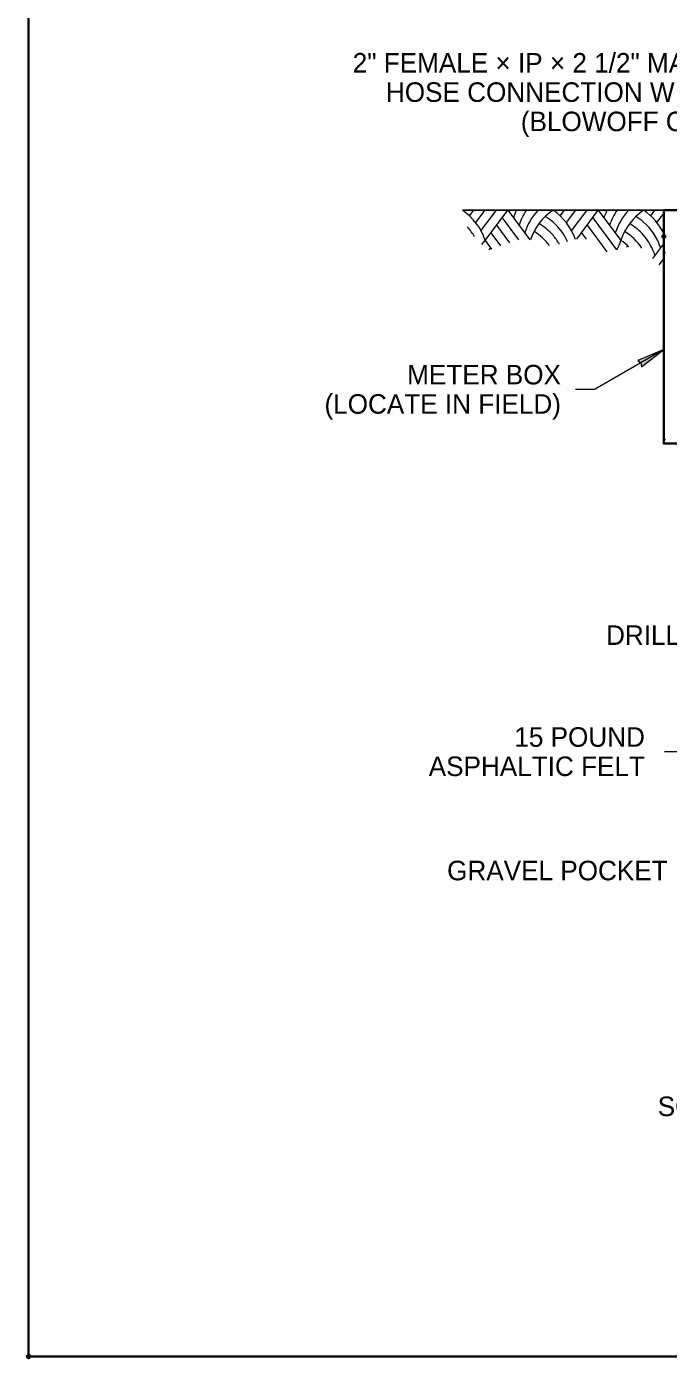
# Model space of a CAD drawing. Extents: x 99860 to 103153, y 99998 to 102077.
# Drawn here: x 99860 to 100386, y 99998 to 101089 of the extents above; entities that cross this region are included whole.
import ezdxf
from ezdxf.enums import TextEntityAlignment as Align

# ---------------------------------------------------------------- set-up
doc = ezdxf.new("R2010")
doc.units = 0
doc.header["$LTSCALE"] = 6.4
doc.header["$PDMODE"] = 32
doc.header["$PDSIZE"] = 3.2
for name, color, linetype, lineweight in [('1', 7, 'Continuous', 13), ('10', 7, 'Continuous', 13), ('15', 7, 'Continuous', 13), ('17', 7, 'Continuous', 35), ('20', 7, 'Continuous', 13)]:
    doc.layers.add(name, color=color, linetype=linetype, lineweight=lineweight)
doc.layers.add('60', color=7, linetype='Continuous')

msp = doc.modelspace()

# ---------------------------------------------------------------- hatches: boundary and pattern name
at = {"layer": '15'}
msp.add_hatch(color=256, dxfattribs=at).paths.add_polyline_path([(100382.538, 100824.244), (100361.275, 100815.414), (100363.682, 100813.357), (100364.26, 100810.244)])

# ---------------------------------------------------------------- linework, layer by layer
at = {"layer": '1'}
for p, q in [((100383.488, 100903.212), (100384.051, 100904.35)), ((100382.351, 100772.05), (100382.501, 100770.912)), ((100383.488, 100750.125), (100384.051, 100751.262))]:
    msp.add_line(p, q, dxfattribs=at)
at = {"layer": '1', "lineweight": 35}
msp.add_lwpolyline([(99862, 99999.5), (103151, 99999.5), (103151, 102075.5), (99862, 102075.5)], close=True, dxfattribs=at)
at = {"layer": '10'}
msp.add_point((100382.538, 100916.925), dxfattribs=at)
at = {"layer": '15', "lineweight": 25}
msp.add_line((100382.538, 100938.462), (100217.513, 100938.462), dxfattribs=at)
at = {"layer": '15'}
for p, q in [((100382.538, 100824.244), (100326.246, 100791.743)), ((100310.246, 100791.743), (100326.246, 100791.743)), ((100383.046, 100494.925), (100399.046, 100494.925))]:
    msp.add_line(p, q, dxfattribs=at)
msp.add_lwpolyline([(100382.538, 100824.244), (100361.275, 100815.414), (100363.682, 100813.357), (100364.26, 100810.244)], close=True, dxfattribs=at)
at = {"layer": '17'}
msp.add_lwpolyline([(100382.538, 100938.462), (100394.726, 100938.462), (100394.726, 100920.862), (100406.188, 100920.862), (100406.188, 100747.25), (100382.538, 100747.25)], close=True, dxfattribs=at)
at = {"layer": '20'}
for p, q in [((100223.33, 100933.845), (100226.794, 100938.462)), ((100228.427, 100928.266), (100236.074, 100938.462)), ((100232.731, 100921.631), (100245.355, 100938.462)), ((100236.074, 100913.714), (100254.636, 100938.462)), ((100254.636, 100938.462), (100272.787, 100914.261)), ((100297.575, 100933.845), (100301.039, 100938.462)), ((100302.672, 100928.266), (100310.319, 100938.462)), ((100306.976, 100921.631), (100319.6, 100938.462)), ((100311.172, 100914.851), (100328.881, 100938.462)), ((100328.881, 100938.462), (100347.442, 100913.714)), ((100371.82, 100933.845), (100375.284, 100938.462)), ((100376.917, 100928.266), (100382.59, 100935.83)), ((100245.355, 100926.088), (100256.181, 100911.653)), ((100249.995, 100932.275), (100263.572, 100914.173)), ((100319.6, 100926.088), (100335.955, 100904.282)), ((100324.24, 100932.275), (100343.866, 100906.108)), ((100381.221, 100921.631), (100382.538, 100923.387)), ((100233.489, 100910.267), (100236.074, 100913.714)), ((100236.074, 100913.714), (100241.399, 100906.614)), ((100240.715, 100919.901), (100248.79, 100909.133)), ((100314.96, 100919.901), (100318.911, 100914.632)), ((100373.461, 100898.909), (100382.538, 100911.012)), ((100239.56, 100905.987), (100240.715, 100907.526)), ((100378.836, 100893.701), (100382.538, 100898.638))]:
    msp.add_line(p, q, dxfattribs=at)
for centre, start, end in [((100191.312, 100899.477), 56.09527, 56.09634), ((100191.312, 100899.477), 17.6434, 56.09527), ((100304.039, 100918.038), 154.22656, 162.3566), ((100308.679, 100911.851), 145.49104, 162.3566), ((100313.319, 100905.664), 135.71272, 162.3566), ((100317.96, 100899.477), 123.90361, 161.85714), ((100260.918, 100893.29), 48.95968, 58.54646), ((100265.557, 100899.477), 18.67677, 56.09634), ((100378.284, 100918.038), 154.22656, 162.3566), ((100382.924, 100911.851), 145.49104, 162.3566), ((100387.564, 100905.664), 135.71272, 162.3566), ((100392.205, 100899.477), 123.90361, 162.3566), ((100335.163, 100893.29), 48.95968, 58.54646), ((100339.802, 100899.477), 24.51811, 56.09634), ((100186.672, 100893.29), 29.64046, 41.9997), ((100256.277, 100887.102), 40.94134, 59.30215), ((100260.917, 100893.29), 24.32116, 48.95974), ((100330.522, 100887.102), 40.94134, 59.30215), ((100335.162, 100893.29), 17.6434, 48.95974), ((100251.637, 100880.915), 37.52241, 58.48736), ((100256.276, 100887.102), 30.04271, 40.94141), ((100302.68, 100927.95), 332.43241, 342.3566), ((100321.242, 100874.728), 45.85785, 56.09639), ((100325.882, 100880.915), 34.40726, 58.48736), ((100330.521, 100887.102), 17.6434, 40.94141), ((100307.321, 100921.763), 343.01373, 345.01126)]:
    msp.add_arc(centre, 46.972, start, end, dxfattribs=at)
at = {"layer": '60'}
msp.add_point((99862, 99999.5), dxfattribs=at)

# ---------------------------------------------------------------- texts
at = {"layer": '20'}
for s, p in [('2" FEMALE × IP × 2 1/2" MALE NST', (100475.77, 101051.199)), ('HOSE CONNECTION WITH CAP', (100475.77, 101027.199)), ('(BLOWOFF OUTLET)', (100475.769, 101003.199)), ('METER BOX', (100298.25, 100795.743)), ('(LOCATE IN FIELD)', (100298.249, 100771.743)), ('DRILL 1/8" HOLE', (100503.344, 100582.353)), ('15 POUND', (100367.049, 100498.925)), ('ASPHALTIC FELT', (100367.05, 100474.925)), ('GRAVEL POCKET', (100385.696, 100389.531)), ('SOLID CONCRETE BEARING', (100670.011, 100196.377))]:
    msp.add_text(s, height=16, dxfattribs=at).set_placement(p, align=Align.RIGHT)

doc.saveas('drawing.dxf')
